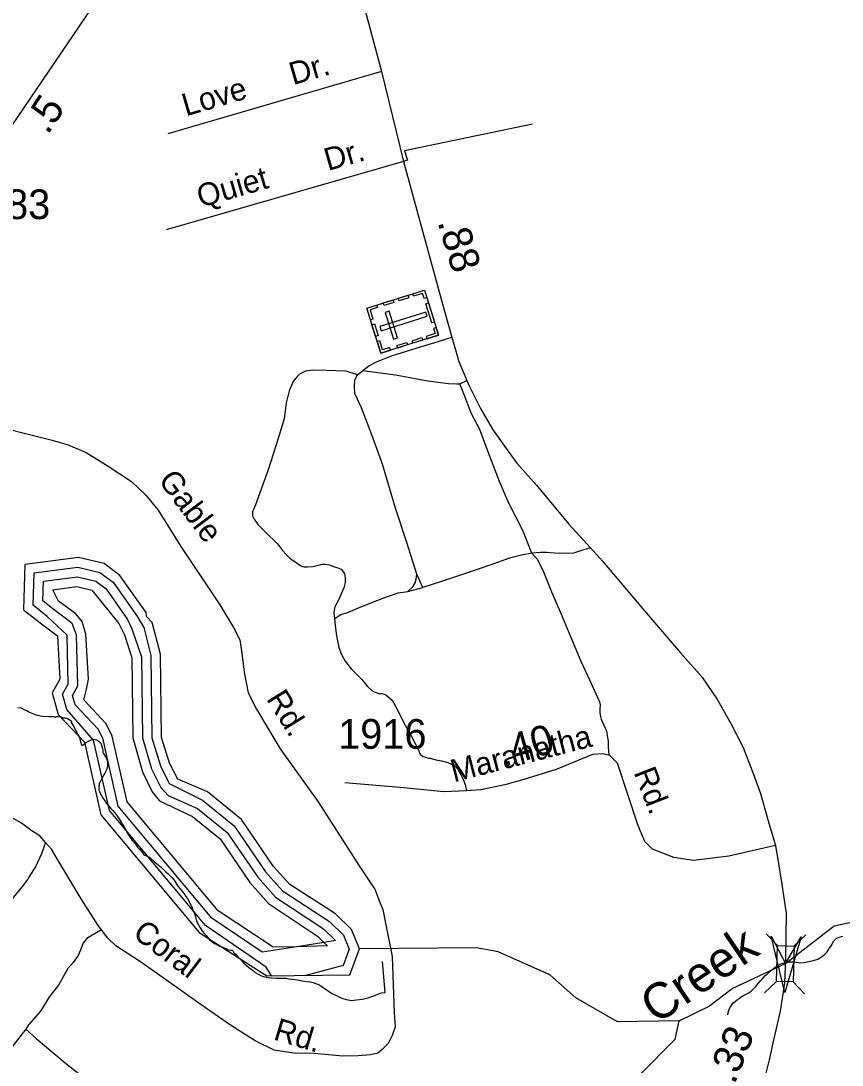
# Model space of a CAD drawing. Extents: x 2206922 to 2357709, y 510027 to 673830.
# Drawn here: x 2309278 to 2312734, y 547820 to 552213 of the extents above; entities that cross this region are included whole.
import ezdxf

# ---------------------------------------------------------------- set-up
doc = ezdxf.new("R2010")
doc.units = 0
for name, color, linetype in [('Exist Cultural Cemetery CELL', 7, 'Continuous'), ('Exist Hydrographic Buffer Line', 7, 'Continuous'), ('Exist Hydrographic Creek Single Shore', 7, 'Continuous'), ('Exist Hydrographic Creek Single Shore Label', 7, 'Continuous'), ('Exist Hydrographic Lake Shore', 7, 'Continuous'), ('Exist Hydrographic Misc Water Feature', 7, 'Continuous'), ('Exist Road Non-System Type 51', 7, 'Continuous'), ('Exist Road Non-System Type 51 Label', 7, 'Continuous'), ('Exist Road Secondary Mileage Hundredths English Label', 7, 'Continuous'), ('Exist Road Secondary Structure Standard Bridge Attributed CELL', 7, 'Continuous'), ('Exist Road Secondary Structure Standard Bridge CELL', 7, 'Continuous'), ('Exist Road Secondary Type 51 Attributed', 7, 'Continuous'), ('Exist Road Secondary Type 51 Label', 7, 'Continuous'), ('Exist Road Secondary Type 51 Number Label', 7, 'Continuous')]:
    doc.layers.add(name, color=color, linetype=linetype)

msp = doc.modelspace()

# ---------------------------------------------------------------- linework, layer by layer
at = {"layer": 'Exist Cultural Cemetery CELL'}
for points in [[(2310793.1, 550814.9), (2310733.6, 551004.9), (2310976.6, 551080.9), (2311036.1, 550891)], [(2310911, 551048.5), (2310869.7, 551035.6), (2310866.3, 551046.4), (2310907.6, 551059.4)], [(2310986.5, 551049.3), (2310975.5, 551045.9), (2310969, 551066.9), (2310930.4, 551054.8), (2310927.1, 551065.4), (2310976.6, 551080.9)], [(2310775, 551017.9), (2310778.4, 551007.1), (2310747.6, 550997.4), (2310759.8, 550958.7), (2310749.1, 550955.4), (2310733.6, 551004.9)], [(2310848.1, 551028.8), (2310806.8, 551015.9), (2310803.4, 551026.8), (2310844.7, 551039.7)], [(2311008, 550942.4), (2310982.6, 551023.3), (2310993.5, 551026.7), (2311018.8, 550945.8)], [(2310788.5, 550927.7), (2310794.1, 550909.8), (2310987.6, 550970.4), (2310982, 550988.3)], [(2310845.8, 550874.2), (2310863.7, 550879.7), (2310828.5, 550992.1), (2310810.7, 550986.5)], [(2310771, 550885.6), (2310755.5, 550935), (2310766.4, 550938.4), (2310781.9, 550889)], [(2311026.2, 550922.5), (2311015.2, 550919.1), (2311021.8, 550898.1), (2310983.2, 550886), (2310986.5, 550875.4), (2311036.1, 550890.9)], [(2310969.4, 550870), (2310928, 550857.1), (2310924.6, 550867.9), (2310965.9, 550880.9)], [(2310834.4, 550827.8), (2310831, 550838.6), (2310800.3, 550829), (2310788.2, 550867.7), (2310777.6, 550864.4), (2310793.1, 550814.9)], [(2310905.2, 550849.9), (2310863.9, 550837), (2310860.5, 550847.9), (2310901.8, 550860.8)]]:
    msp.add_lwpolyline(points, close=True, dxfattribs=at)
at = {"layer": 'Exist Hydrographic Buffer Line'}
for points in [[(2310332.5, 548195.5), (2310310.3, 548231.6), (2310055.1, 548407.7), (2309651.3, 548890.9), (2309584.3, 549187.1), (2309471.1, 549315.6), (2309452.6, 549380.8), (2309477, 549423.2), (2309472.3, 549628.7), (2309388.4, 549708.1), (2309329.8, 549754.5), (2309334.3, 549890.8), (2309518.2, 549914.4), (2309611.1, 549892.7), (2309666.3, 549851.8), (2309765.9, 549709.9), (2309795.2, 549661.6), (2309825.2, 549543.6), (2309829.3, 549197.5), (2309866.2, 549078.6), (2309902.5, 549005.5), (2310042.3, 548934.9), (2310176.4, 548826.5), (2310308.3, 548633.3), (2310379.4, 548553.1), (2310577.3, 548424.9), (2310635.6, 548367.2), (2310660.4, 548308.4), (2310635.1, 548239.2), (2310477.9, 548197.3)], [(2310293.7, 548295), (2310081.7, 548438.1), (2309688, 548909.2), (2309623.2, 549195.9), (2309603.5, 549233.1), (2309506.7, 549336), (2309495.5, 549375.4), (2309517.6, 549415.8), (2309512.3, 549630.9), (2309493.6, 549677.9), (2309412.8, 549740), (2309370.6, 549773.4), (2309373, 549855.5), (2309516, 549873.8), (2309594.1, 549855.7), (2309637.4, 549823.5), (2309727.4, 549695.5), (2309745, 549655.8), (2309785.2, 549538.4), (2309789.3, 549196.9), (2309828.3, 549066.1), (2309866.8, 548987.5), (2309898.2, 548954.2), (2310021.6, 548900.3), (2310146.7, 548799), (2310275.3, 548610.7), (2310349.5, 548526.5), (2310552.1, 548393.4), (2310601.7, 548344.4), (2310552.7, 548336.5), (2310439.7, 548318.4), (2310293.7, 548295)], [(2310339.3, 548315.9), (2310108.6, 548468.5), (2309725.1, 548927.3), (2309662.4, 549204.7), (2309637.4, 549255.4), (2309542.6, 549356.3), (2309554.9, 549402.1), (2309562.3, 549443.2), (2309552.1, 549633.1), (2309536.3, 549686.5), (2309509.6, 549718.4), (2309437, 549771.9), (2309412, 549820.1), (2309514.1, 549833.2), (2309576.9, 549818.6), (2309690.3, 549678.7), (2309714.3, 549630.2), (2309745.6, 549533.1), (2309749.3, 549196.5), (2309790.3, 549053.7), (2309831.1, 548969.5), (2309861.1, 548931.5), (2310000.5, 548865.8), (2310117, 548771.7), (2310242.1, 548588.2), (2310319.8, 548499.8), (2310527.1, 548362.1), (2310552.7, 548336.5), (2310568.1, 548321.5), (2310439.7, 548318.4), (2310339.3, 548315.9)]]:
    msp.add_lwpolyline(points, dxfattribs=at)
at = {"layer": 'Exist Hydrographic Creek Single Shore'}
for points in [[(2312048.4, 548006), (2312172.4, 548066.8), (2312271.3, 548143), (2312496.2, 548247.3), (2312701.2, 548406.5), (2312851.3, 548438.8)], [(2312048.4, 548006), (2311789.4, 548002.1), (2311613.2, 548103.3), (2311504.4, 548200.6), (2311286.4, 548296.9), (2311195.3, 548312.9), (2310703.2, 548309.4)], [(2311805.6, 547619), (2311883.3, 547779.5), (2312032.4, 547929.9), (2312048.4, 548006)]]:
    msp.add_lwpolyline(points, dxfattribs=at)
at = {"layer": 'Exist Hydrographic Lake Shore'}
msp.add_lwpolyline([(2310703.2, 548309.4), (2310669.4, 548390.1), (2310602.3, 548456.3), (2310409.4, 548579.8), (2310341.3, 548655.8), (2310206.4, 548853.8), (2310063.3, 548969.4), (2309938.4, 549023.5), (2309904.3, 549091), (2309869.3, 549197.9), (2309865.4, 549548.9), (2309831.3, 549682), (2309806.3, 549707.3), (2309805.3, 549723.7), (2309695.2, 549880), (2309628.3, 549929.8), (2309520.3, 549955), (2309295.3, 549926.2), (2309289.2, 549735.7), (2309364.2, 549676.4), (2309432.3, 549626.5), (2309442.4, 549443.2), (2309409.3, 549386.1), (2309435.2, 549295.3), (2309545.3, 549178.3), (2309614.2, 548872.7), (2310028.2, 548377.4), (2310313.2, 548195.3), (2310663.2, 548199.5), (2310703.2, 548309.4)], dxfattribs=at)
at = {"layer": 'Exist Hydrographic Misc Water Feature'}
for points in [[(2309264.8, 549325.1), (2309278.5, 549323), (2309295.1, 549315.3), (2309302.9, 549311.3), (2309309.1, 549307.5), (2309316.9, 549303.5), (2309330.8, 549297.7), (2309341.3, 549293.7), (2309349.5, 549291.7), (2309359.3, 549290.2), (2309369.2, 549288.3), (2309395.2, 549286.4), (2309401.1, 549286.3), (2309409.3, 549286.8), (2309415.3, 549286.7), (2309423.5, 549284.6), (2309427.2, 549286.9), (2309435.4, 549286.9), (2309447.3, 549285.1), (2309455.1, 549281.1), (2309463.3, 549281.1), (2309473.1, 549279.2)], [(2309473.1, 549279.2), (2309491.6, 549267.5)], [(2309491.6, 549267.5), (2309489.7, 549261.3), (2309495.7, 549253.5), (2309497.5, 549249.5), (2309513.9, 549219.9), (2309518, 549211.6), (2309522.1, 549203.7), (2309524.2, 549197.7), (2309526.2, 549191.7), (2309528.3, 549186.1), (2309530.3, 549176.1), (2309532.4, 549170.1), (2309534.6, 549166.1), (2309538.3, 549165.9), (2309542.2, 549168.2), (2309548.4, 549174.2), (2309554.5, 549178.1), (2309560.3, 549182.1), (2309568.1, 549186.2), (2309574, 549188.5), (2309584.3, 549190.7), (2309590.2, 549190.6), (2309597.8, 549188.6), (2309606.2, 549182.9), (2309612.5, 549176.7), (2309616.2, 549170.8), (2309618.1, 549164.9), (2309620.5, 549156.8), (2309622.6, 549145.2), (2309622.6, 549141.1), (2309622.8, 549137), (2309626.5, 549131.2), (2309634.9, 549117), (2309640.8, 549105.1), (2309643.1, 549093), (2309643.3, 549079.1), (2309641.3, 549069.3), (2309639.8, 549065.1), (2309637.6, 549058.9), (2309631.6, 549048.9), (2309627.7, 549040.9), (2309621.8, 549030.9), (2309610.1, 549008.8), (2309608, 549005), (2309606.4, 548986.6), (2309606, 548976.9), (2309608.4, 548970.9), (2309612.8, 548960.9), (2309618.7, 548951.1), (2309624.6, 548941.2), (2309632.8, 548931.1), (2309638.8, 548921.3), (2309649, 548909.2), (2309655, 548901.4), (2309665.2, 548891.4), (2309673.4, 548881.6), (2309679.8, 548873.8), (2309695.8, 548849.9), (2309712, 548821.9), (2309726.4, 548796.2), (2309732.3, 548786.4), (2309736.6, 548780.5), (2309742.3, 548772.3), (2309746.7, 548764.4), (2309760.8, 548750.4), (2309768.8, 548736.7), (2309777.2, 548728.9), (2309787, 548716.9), (2309795.5, 548705.1), (2309805.3, 548701.2), (2309819.2, 548695.4), (2309825, 548689.3), (2309839.5, 548677.4), (2309869.9, 548651.8), (2309883.6, 548637.9), (2309890, 548632.1), (2309896.1, 548626.3), (2309906, 548616.3), (2309914.4, 548608.5), (2309922.6, 548598.4), (2309938.8, 548572.8), (2309946.8, 548562.7), (2309954.8, 548555), (2309964.8, 548540.9), (2309973, 548529.1), (2309979, 548520.9), (2309997.6, 548485.3), (2309999.7, 548479.3), (2310001.5, 548473.4), (2310005.8, 548463.4), (2310009.7, 548453.5), (2310013.6, 548443.5), (2310016.3, 548433.4), (2310017.7, 548427.5), (2310019.8, 548419.5), (2310032.3, 548397.8), (2310042.5, 548382), (2310050.5, 548371.9), (2310058.7, 548364.2), (2310066.7, 548354)], [(2310066.7, 548354), (2310072.7, 548346.3), (2310081.1, 548340.5), (2310093, 548332.3), (2310101.2, 548328.6), (2310115.1, 548320.8), (2310131.1, 548314.8), (2310143.4, 548308.9), (2310151.2, 548305.2), (2310161.3, 548303.3), (2310167.2, 548303.3), (2310171.1, 548299.4), (2310175.8, 548291.4), (2310181.6, 548287.3), (2310191.4, 548275.7), (2310205.8, 548261.8), (2310209.7, 548257.9), (2310215.6, 548249.8), (2310236.1, 548232.1), (2310251.9, 548220.3), (2310264.2, 548210.4), (2310280.2, 548200.7), (2310288.4, 548196.6), (2310298.2, 548192.7), (2310318.5, 548188.8), (2310334.3, 548187.3), (2310350.7, 548185.2), (2310380.5, 548185.6), (2310394.6, 548185.9), (2310406.5, 548183.7), (2310418.6, 548181.9), (2310442.6, 548178.2), (2310462.3, 548174.4), (2310480.7, 548172.5), (2310494.5, 548170.9), (2310508.6, 548167.1), (2310526.5, 548161.2), (2310533, 548157.3), (2310544.7, 548151.5), (2310555, 548143.5), (2310560.7, 548139.4), (2310566.9, 548135.6), (2310587, 548121.6), (2310593.1, 548117.9), (2310609.3, 548112.2), (2310623.2, 548104.4), (2310629.2, 548102.3), (2310647.4, 548096.3), (2310655.2, 548094.7), (2310669.4, 548092.6), (2310679, 548092.8), (2310715.1, 548097.1), (2310721.5, 548099.4), (2310739.1, 548103.6), (2310750.8, 548107.6), (2310767.2, 548113.6), (2310773.1, 548116), (2310784.8, 548119.9), (2310796.5, 548124.2), (2310810.9, 548126.1), (2310799.8, 548255.9)], [(2312253, 548031.8), (2312255.1, 548041.7), (2312260.8, 548057.9), (2312266.7, 548067.9), (2312274.7, 548080.1), (2312284.6, 548088), (2312294.4, 548096.2), (2312302.6, 548102.3), (2312314.1, 548110.3), (2312328.1, 548116.7), (2312338.3, 548122.4), (2312352, 548130.9), (2312361.7, 548140.8), (2312371.9, 548151), (2312381.6, 548163), (2312389.6, 548173.1), (2312399.4, 548183.4), (2312409, 548195.3), (2312423, 548207.4), (2312437.3, 548219.5), (2312452.9, 548231.7), (2312465, 548240), (2312476.5, 548246), (2312492.5, 548250.1), (2312512.4, 548254.4), (2312526.5, 548254.7), (2312540.5, 548252.6), (2312560.8, 548250.7), (2312574.3, 548251.1), (2312594.6, 548255.4), (2312614.5, 548259.7), (2312632.3, 548265.5), (2312648.1, 548275.7), (2312662.3, 548286.2), (2312671.9, 548296), (2312681.8, 548312), (2312687.7, 548322), (2312699.6, 548342.5), (2312709.4, 548352.4), (2312721.5, 548358.7), (2312737.5, 548362.8)]]:
    msp.add_lwpolyline(points, dxfattribs=at)
at = {"layer": 'Exist Road Non-System Type 51'}
for p, q in [((2310795.6, 551999.7), (2309896.9, 551738.1)), ((2311431.6, 551778.5), (2310893.2, 551666.7)), ((2310889, 551622.2), (2309889.2, 551334.1)), ((2310694.3, 550723.8), (2310717.5, 550742.8)), ((2311125, 550686.2), (2311155.3, 550700.4)), ((2310969.8, 549829.5), (2310944.8, 549885.6)), ((2310906, 549813.1), (2310969.8, 549829.5))]:
    msp.add_line(p, q, dxfattribs=at)
for points in [[(2310893.2, 551666.7), (2310905.6, 551627), (2310889, 551622.2)], [(2310717.5, 550742.8), (2310742.6, 550761.9), (2310774.8, 550779.3), (2310837.9, 550804.1), (2310960.5, 550842.5), (2311034.8, 550864.8), (2311092.4, 550883.1)], [(2310694.3, 550723.8), (2310647.3, 550739.6), (2310564.4, 550742.1), (2310506.2, 550743.4), (2310476.5, 550739.6), (2310450.5, 550727.3), (2310441.8, 550718.6), (2310424.5, 550696.3), (2310407.1, 550656.7), (2310394.8, 550605.9), (2310386.1, 550539), (2310361.3, 550456), (2310319.2, 550324.7), (2310266, 550177.3), (2310253.6, 550147.6), (2310252.4, 550131.5), (2310259.8, 550116.6), (2310274.7, 550094.3), (2310306.9, 550063.3), (2310357.6, 550012.6), (2310378.7, 549985.3), (2310394.8, 549968), (2310413.3, 549949.4), (2310426.9, 549942), (2310443, 549930.8), (2310456.7, 549920.9), (2310469, 549916), (2310483.9, 549916), (2310506.2, 549918.4), (2310524.7, 549922.1), (2310545.8, 549928.3), (2310558.2, 549927.1), (2310576.7, 549924.6), (2310594.1, 549918.4), (2310611.4, 549912.2), (2310626.3, 549906), (2310639.9, 549888.7), (2310642.3, 549871.4), (2310643.6, 549850.3), (2310637.4, 549828), (2310626.3, 549803.2), (2310616.4, 549778.5), (2310599, 549748.7), (2310595.3, 549726.4), (2310597.8, 549697.9)], [(2310717.5, 550742.8), (2310854.3, 550723.8), (2310991.1, 550698.5), (2311077.4, 550688), (2311111.1, 550685.9), (2311125, 550686.2)], [(2310944.8, 549885.6), (2310902.7, 550018.3), (2310854.3, 550163.6), (2310799.6, 550348.9), (2310755.4, 550471.1), (2310711.2, 550584.8), (2310683.8, 550645.9), (2310681.7, 550673.3), (2310683.8, 550702.7), (2310694.3, 550723.8)], [(2311429, 549974), (2311391.1, 550068.8), (2311330, 550186.7), (2311292.1, 550275.2), (2311241.6, 550407.9), (2311210, 550494.2), (2311174.3, 550559.5), (2311142.7, 550643.8), (2311125, 550686.2)], [(2309209.5, 550500.5), (2309309.3, 550474.9), (2309409.1, 550449.2), (2309476.5, 550429), (2309553.4, 550398), (2309645, 550340), (2309743.5, 550275.2), (2309804.1, 550218.6), (2309855.4, 550155.2), (2309951.1, 550001.4), (2310115.6, 549757.2), (2310173.6, 549661.4), (2310199.2, 549608.8), (2310208.6, 549553.5), (2310218.1, 549473.9), (2310234.2, 549386.2), (2310269.3, 549317.4), (2310369.1, 549150.1), (2310528.7, 548928.4), (2310699.5, 548662.4), (2310768.7, 548557.2), (2310785.7, 548510.7), (2310801.9, 548474.2), (2310814, 548410.8), (2310841, 548277.3), (2310849.1, 548039.9), (2310853.1, 547980.5), (2310841, 547944.1), (2310823.4, 547911.7), (2310799.2, 547886.1), (2310780.3, 547869.9), (2310749.3, 547863.1), (2310698.1, 547859.1), (2310633.3, 547857.7), (2310512, 547868.5), (2310425.7, 547869.9), (2310343.5, 547883.4), (2310263.7, 547922), (2310160.1, 547988.6), (2310026.6, 548080.3), (2309901.2, 548170.7), (2309777.2, 548257.1), (2309677.4, 548321.8), (2309643.7, 548354.2), (2309603.2, 548406.8), (2309531.8, 548520.1), (2309430.7, 548687.4), (2309406.4, 548729.2), (2309382.1, 548756.2)], [(2311675.4, 549996), (2311637.4, 549984.6), (2311603.7, 549974), (2311557.4, 549971.9), (2311523.7, 549974), (2311492.1, 549976.1), (2311464.7, 549976.1), (2311429, 549974)], [(2311429, 549974), (2311384.8, 549965.6), (2311334.2, 549953), (2311264.8, 549927.7), (2311161.6, 549891.9), (2311056.5, 549857.7), (2310969.8, 549829.5)], [(2311429, 549974), (2311451.7, 549947.4), (2311478.1, 549896), (2311511, 549811.1), (2311552.4, 549717), (2311634.6, 549518.9), (2311671.5, 549441.2), (2311690.5, 549397.8), (2311712.9, 549348.4), (2311715.5, 549335.2), (2311714.2, 549318.8), (2311714.9, 549302.3), (2311716.9, 549287.2), (2311720.1, 549275.4), (2311724.1, 549266.1), (2311732, 549250.3), (2311737.9, 549235.2), (2311743.2, 549226), (2311745.8, 549204.9), (2311749.7, 549184.5), (2311750.4, 549168.6), (2311749.1, 549158.1), (2311751.1, 549142.4), (2311752.9, 549124.1)], [(2310906, 549813.1), (2310928.3, 549832.1), (2310937, 549849.1), (2310941.3, 549865.1), (2310944.8, 549885.6)], [(2310597.8, 549697.9), (2310622.5, 549714.1), (2310657.2, 549725.2), (2310696.8, 549742.5), (2310762.4, 549768.6), (2310816.9, 549789.6), (2310866.4, 549806.9), (2310906, 549813.1)], [(2310597.8, 549697.9), (2310602.1, 549658.9), (2310607.1, 549626.8), (2310616.1, 549576.6), (2310627.2, 549547.5), (2310643.2, 549519.4), (2310668.3, 549487.3), (2310712.4, 549442.1), (2310737.5, 549413), (2310755.6, 549395.9), (2310765.6, 549389.9), (2310786.7, 549383.9), (2310799.7, 549382.9), (2310813.7, 549377.9), (2310821.8, 549370.9), (2310840.8, 549354.8), (2310861.9, 549317.7), (2310888, 549262.4), (2310922.1, 549203.2), (2310942.2, 549165.1), (2310954.2, 549140), (2310959.2, 549128.9), (2310970.2, 549118.9), (2310995.3, 549111.9), (2311000.3, 549110.9), (2311024.4, 549104.9), (2311048.5, 549099.8), (2311074.6, 549092.8), (2311097.7, 549083.8), (2311106.7, 549077.8), (2311118.7, 549062.7), (2311130.8, 549039.6), (2311137.8, 549025.6), (2311144.8, 549007.5), (2311148.8, 548995.5), (2311153.5, 548974.7)], [(2309382.1, 548756.2), (2309357.8, 548784.5), (2309324.1, 548806.1), (2309281, 548838.5), (2309228.4, 548866.8), (2309152.9, 548905.9), (2309037, 548976.1), (2308956.1, 549016.6), (2308910.2, 549044.9), (2308850.9, 549085.4), (2308819.9, 549117.7), (2308799.7, 549148.8), (2308768.6, 549223)], [(2309382.1, 548756.2), (2309364.6, 548709), (2309341.7, 548656.4), (2309312, 548610.5), (2309307.9, 548601.9), (2309285, 548573.6), (2309227.1, 548502.6), (2309185.3, 548448.6), (2309096.3, 548383.9), (2309031.6, 548335.3), (2308969.5, 548298.9), (2308865.7, 548232.8), (2308795.6, 548169.4), (2308726.8, 548087.4), (2308655.9, 547990.7), (2308620.3, 547952.3), (2308576.7, 547917.9), (2308537.1, 547881.5), (2308477.5, 547842.9), (2308433.5, 547823.3)], [(2309615.3, 548388.3), (2309573.9, 548364.4), (2309555.5, 548352.4), (2309540.7, 548334), (2309530.6, 548308.2), (2309519.6, 548280.6), (2309498.4, 548251.1), (2309476.3, 548226.3), (2309435.8, 548156.3), (2309399, 548108.4), (2309361.3, 548046.8), (2309310.7, 547989.7), (2309298.8, 547971.3)], [(2309298.8, 547971.3), (2309238.5, 547893.5), (2309126.7, 547781.6), (2309099.8, 547748.5), (2309017, 547657.4), (2308913.5, 547543.4), (2308822.4, 547464.7), (2308687.8, 547272.1)], [(2309298.8, 547971.3), (2309342, 547931.7), (2309472.7, 547823.1), (2309618, 547710.8), (2309730.3, 547605.8), (2309881.2, 547498.1), (2310005.4, 547395.9), (2310154.4, 547271.6), (2310291.5, 547160.3), (2310477.4, 547006.5), (2310687.1, 546849.1)]]:
    msp.add_lwpolyline(points, dxfattribs=at)
at = {"layer": 'Exist Road Secondary Structure Standard Bridge Attributed CELL'}
msp.add_lwpolyline([(2312562.4, 548359.2), (2312492.9, 548125.4), (2312436.2, 548362.6), (2312496.2, 548247.3)], close=True, dxfattribs=at)
at = {"layer": 'Exist Road Secondary Structure Standard Bridge CELL'}
for p, q in [((2312462.4, 548322.9), (2312414.9, 548373)), ((2312531.4, 548321.1), (2312581.4, 548368.6)), ((2312408.1, 548124.4), (2312458.2, 548171.9)), ((2312576.2, 548120), (2312528.7, 548170))]:
    msp.add_line(p, q, dxfattribs=at)
msp.add_lwpolyline([(2312458.2, 548171.9), (2312462.1, 548322.9), (2312532.7, 548321.1), (2312528.7, 548170)], close=True, dxfattribs=at)
at = {"layer": 'Exist Road Secondary Type 51 Attributed'}
for points in [[(2309959.2, 553328.1), (2309850, 552974.7), (2309750.2, 552630.6), (2309713.8, 552518.7), (2309682.8, 552444.5), (2309576.3, 552269.1), (2309239.2, 551771.3), (2309054.5, 551494.8), (2308964.1, 551346.4), (2308948, 551314), (2308935.8, 551284.3), (2308922.3, 551245.2), (2308915.6, 551196.6), (2308917, 551152.1), (2308922.3, 551104.9), (2308953.4, 550953.8), (2309014, 550756.8), (2309035.6, 550688), (2309063.9, 550603), (2309090.9, 550520.7)], [(2310727, 552256.7), (2310795.6, 551999.7), (2310889, 551622.2), (2311058.5, 551001.8), (2311092.4, 550883.1), (2311121.6, 550780.7), (2311155.3, 550700.4), (2311165.8, 550675.4), (2311212.2, 550582.7), (2311262.7, 550496.3), (2311313.2, 550424.7), (2311365.8, 550353.1), (2311447.9, 550260.5), (2311584.7, 550096.2), (2311675.4, 549996), (2311725.8, 549940.3), (2311902.6, 549731.8), (2312054.1, 549554.9), (2312144.7, 549453.8), (2312209.9, 549356.9), (2312266.7, 549257.9), (2312317.3, 549156.8), (2312355.2, 549057.9), (2312390.9, 548963.1), (2312422.5, 548847.2), (2312454.1, 548744)], [(2312454.1, 548744), (2312258.3, 548699.2), (2312188.9, 548691.4), (2312108.9, 548680.9), (2312026.8, 548693.5), (2311976.3, 548712.5), (2311936.3, 548729.3), (2311904.7, 548760.9), (2311875.2, 548830.4), (2311788.4, 549089.9), (2311757.3, 549123.1), (2311752.9, 549124.1), (2311727.9, 549129.5), (2311683.7, 549127.4), (2311530.9, 549063.1), (2311395.3, 549022.1), (2311315.6, 548998.8), (2311213.8, 548977.7), (2311153.5, 548974.7), (2311058.1, 548970), (2310890.1, 548986.2), (2310641.7, 549007.3)], [(2312454.1, 548744), (2312479.3, 548590.3), (2312498.3, 548457.6), (2312496.1, 548270.1)], [(2312496.1, 548270.1), (2312492, 548164.9), (2312473, 548046.9), (2312447.8, 547937.4), (2312426.7, 547842.6), (2312391, 547697.1), (2312357.3, 547617.3), (2312318.7, 547532.3), (2312279.4, 547453.9), (2312232.2, 547373.4), (2312165.4, 547278.9), (2312096.5, 547182.5), (2312054.7, 547124.4)]]:
    msp.add_lwpolyline(points, dxfattribs=at)

# ---------------------------------------------------------------- texts
at = {"layer": 'Exist Hydrographic Creek Single Shore Label'}
msp.add_text('Creek', height=150, rotation=34.0947, dxfattribs=at).set_placement((2311952.1, 547989.1))
at = {"layer": 'Exist Road Non-System Type 51 Label'}
for s, rotation, p in [('Dr.', 16.2296, (2310423.6, 551942.7)), ('Love', 16.2296, (2309972.4, 551811.3)), ('Dr.', 16.0756, (2310570.4, 551581.6)), ('Quiet', 16.0756, (2310034.8, 551427.3)), ('Gable', 306.9912, (2309853.2, 550279.6)), ('Rd.', 301.8408, (2310308.9, 549361.3)), ('Coral', 322.8697, (2309743.8, 548363.5)), ('Rd.', 343.3113, (2310336.7, 547928.6))]:
    msp.add_text(s, height=95, rotation=rotation, dxfattribs=at).set_placement(p)
at = {"layer": 'Exist Road Secondary Mileage Hundredths English Label'}
for s, rotation, p in [('.5', 56.81, (2309391.3, 551730.5)), ('.88', 286.602, (2311030.9, 551367.7)), ('.40', 16.3142, (2311309, 549073.3)), ('.33', 68.2931, (2312281.3, 547735.6))]:
    msp.add_text(s, height=125, rotation=rotation, dxfattribs=at).set_placement(p)
at = {"layer": 'Exist Road Secondary Type 51 Label'}
for s, rotation, p in [('Maranatha', 14.5058, (2311100.3, 549009.6)), ('Rd.', 291.3428, (2311856.1, 549051.7))]:
    msp.add_text(s, height=95, rotation=rotation, dxfattribs=at).set_placement(p)
at = {"layer": 'Exist Road Secondary Type 51 Number Label'}
for s, p in [('1983', (2309029.9, 551379.4)), ('1916', (2310613.4, 549151))]:
    msp.add_text(s, height=125, dxfattribs=at).set_placement(p)

doc.saveas('drawing.dxf')
